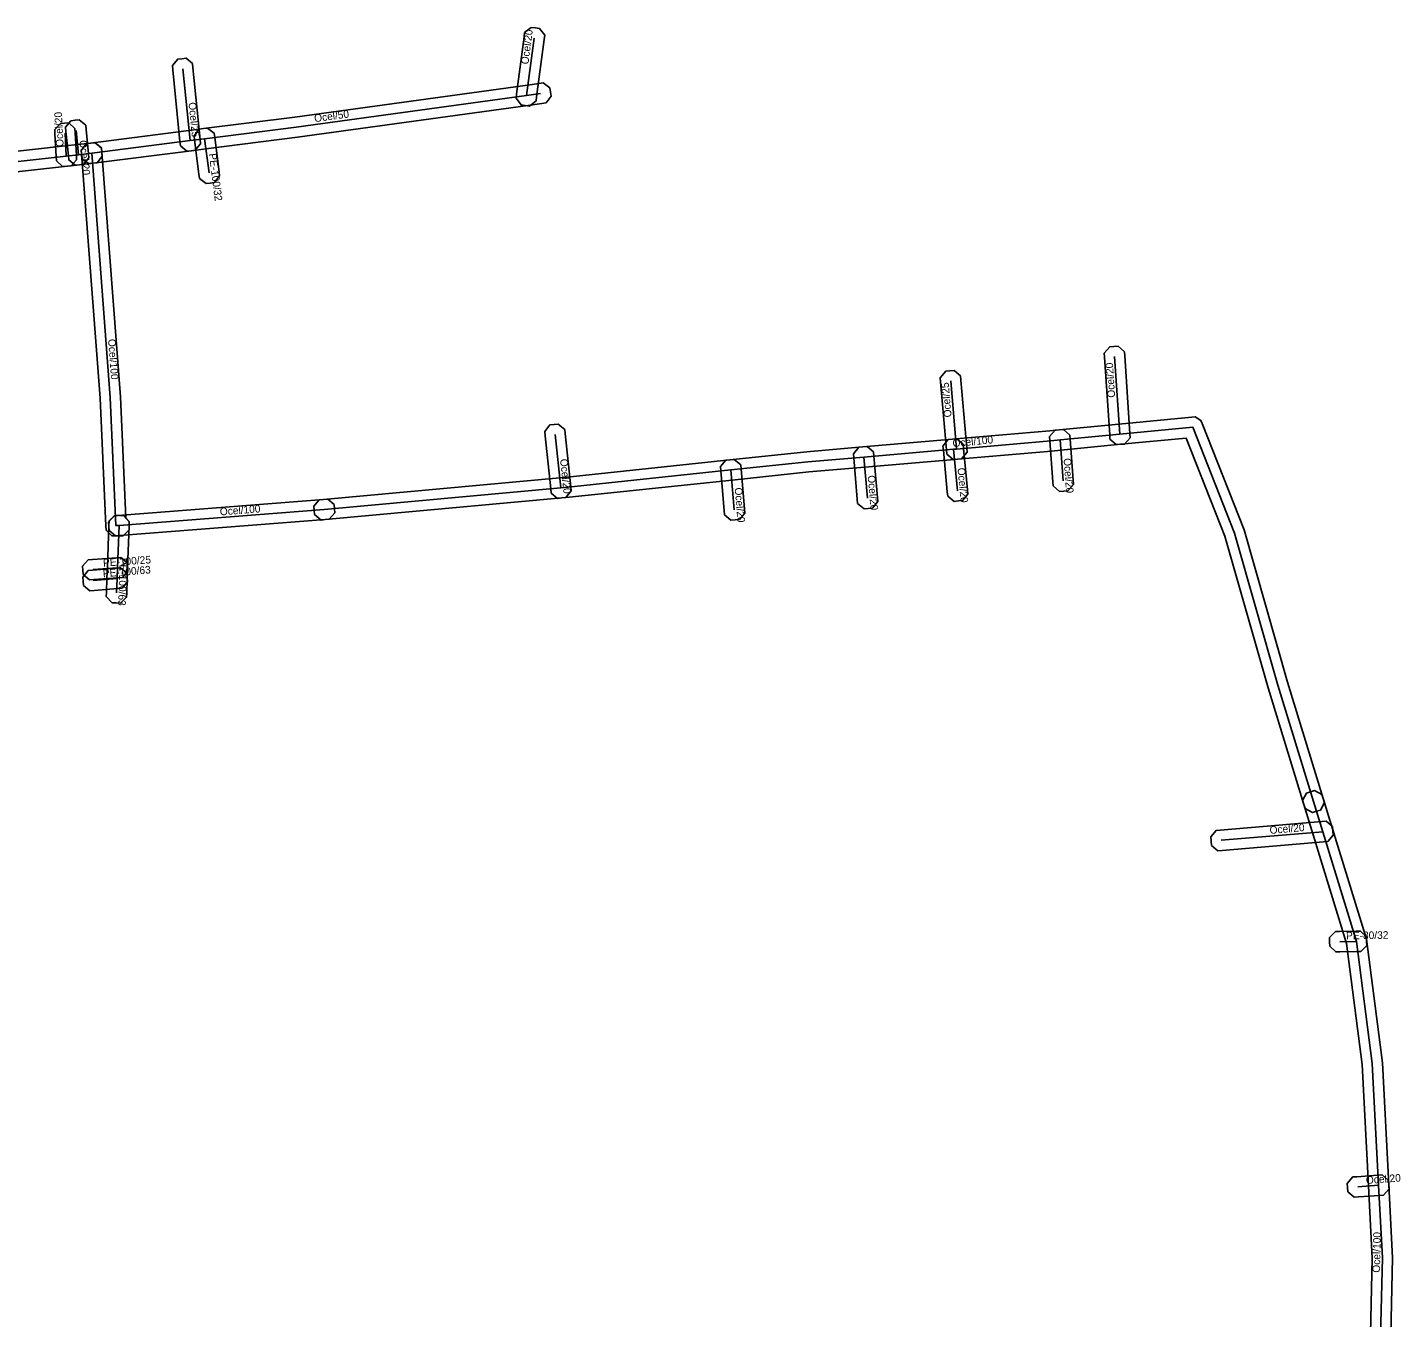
# Model space of a CAD drawing. Extents: x -569373 to -565022, y -1135090 to -1131496.
# Drawn here: x -565577.8 to -565442.3, y -1133706.4 to -1133579.1 of the extents above; entities that cross this region are included whole.
import ezdxf

# ---------------------------------------------------------------- set-up
doc = ezdxf.new("R2010")
doc.units = 0
for name, color, linetype in [('1', 7, 'Continuous'), ('24', 7, 'Continuous'), ('30', 7, 'Continuous')]:
    doc.layers.add(name, color=color, linetype=linetype)

msp = doc.modelspace()

# ---------------------------------------------------------------- linework, layer by layer
at = {"layer": '1'}
for points in [[(-565526.775, -1133579.909), (-565526.828, -1133580.32), (-565527.568, -1133585.98), (-565527.622, -1133586.39), (-565528.279, -1133586.895), (-565528.69, -1133586.842), (-565529.1, -1133586.788), (-565529.605, -1133586.131), (-565529.552, -1133585.72), (-565528.812, -1133580.06), (-565528.758, -1133579.65), (-565528.101, -1133579.145), (-565527.69, -1133579.198), (-565527.28, -1133579.252)], [(-565562.714, -1133590.822), (-565562.755, -1133590.41), (-565563.465, -1133583.32), (-565563.506, -1133582.908), (-565562.982, -1133582.266), (-565562.57, -1133582.225), (-565562.158, -1133582.184), (-565561.516, -1133582.708), (-565561.475, -1133583.12), (-565560.765, -1133590.21), (-565560.724, -1133590.622), (-565561.248, -1133591.264), (-565561.66, -1133591.305), (-565562.072, -1133591.346)], [(-565571.998, -1133590.611), (-565571.587, -1133590.558), (-565561.889, -1133589.318), (-565560.449, -1133589.128), (-565551.431, -1133587.979), (-565528.697, -1133584.859), (-565527.327, -1133584.669), (-565526.917, -1133584.612), (-565526.256, -1133585.113), (-565526.199, -1133585.523), (-565526.142, -1133585.933), (-565526.643, -1133586.594), (-565527.053, -1133586.651), (-565528.423, -1133586.841), (-565551.169, -1133589.961), (-565560.191, -1133591.112), (-565561.631, -1133591.302), (-565571.333, -1133592.542), (-565571.744, -1133592.595), (-565572.399, -1133592.088), (-565572.452, -1133591.677), (-565572.505, -1133591.266)], [(-565572.056, -1133588.788), (-565572.015, -1133589.2), (-565571.775, -1133591.6), (-565571.734, -1133592.013), (-565572.258, -1133592.654), (-565572.67, -1133592.695), (-565573.083, -1133592.736), (-565573.724, -1133592.212), (-565573.765, -1133591.8), (-565574.005, -1133589.4), (-565574.046, -1133588.987), (-565573.522, -1133588.346), (-565573.11, -1133588.305), (-565572.697, -1133588.264)], [(-565574.947, -1133592.297), (-565574.969, -1133591.883), (-565575.089, -1133589.633), (-565575.111, -1133589.22), (-565574.557, -1133588.603), (-565574.143, -1133588.581), (-565573.73, -1133588.559), (-565573.113, -1133589.113), (-565573.091, -1133589.527), (-565572.971, -1133591.777), (-565572.949, -1133592.19), (-565573.503, -1133592.807), (-565573.917, -1133592.829), (-565574.33, -1133592.851)], [(-565559.38, -1133589.583), (-565559.328, -1133589.994), (-565558.898, -1133593.374), (-565558.846, -1133593.785), (-565559.353, -1133594.44), (-565559.764, -1133594.492), (-565560.175, -1133594.544), (-565560.83, -1133594.037), (-565560.882, -1133593.626), (-565561.312, -1133590.246), (-565561.364, -1133589.835), (-565560.857, -1133589.18), (-565560.446, -1133589.128), (-565560.035, -1133589.076)], [(-565616.839, -1133596.218), (-565616.429, -1133596.16), (-565599.549, -1133593.79), (-565595.205, -1133593.178), (-565574.079, -1133590.836), (-565572.881, -1133590.706), (-565571.574, -1133590.556), (-565571.162, -1133590.509), (-565570.513, -1133591.025), (-565570.466, -1133591.436), (-565570.419, -1133591.848), (-565570.935, -1133592.497), (-565571.346, -1133592.544), (-565572.659, -1133592.694), (-565573.861, -1133592.824), (-565594.955, -1133595.162), (-565599.271, -1133595.77), (-565616.151, -1133598.14), (-565616.561, -1133598.198), (-565617.222, -1133597.699), (-565617.28, -1133597.289), (-565617.338, -1133596.879)], [(-565568.632, -1133615.58), (-565568.102, -1133627.534), (-565567.77, -1133627.866), (-565567.77, -1133628.28), (-565567.77, -1133628.694), (-565568.356, -1133629.28), (-565568.77, -1133629.28), (-565569.07, -1133629.28), (-565569.471, -1133629.28), (-565570.051, -1133628.725), (-565570.069, -1133628.324), (-565570.628, -1133615.7), (-565572.457, -1133591.626), (-565572.488, -1133591.213), (-565571.949, -1133590.584), (-565571.536, -1133590.553), (-565571.123, -1133590.522), (-565570.494, -1133591.061), (-565570.463, -1133591.474)], [(-565471.01, -1133619.749), (-565471.038, -1133619.336), (-565471.548, -1133611.676), (-565471.575, -1133611.263), (-565471.029, -1133610.64), (-565470.616, -1133610.612), (-565470.203, -1133610.585), (-565469.58, -1133611.131), (-565469.552, -1133611.544), (-565469.042, -1133619.204), (-565469.015, -1133619.617), (-565469.561, -1133620.24), (-565469.974, -1133620.268), (-565470.387, -1133620.295)], [(-565487.1, -1133621.229), (-565487.136, -1133620.816), (-565487.716, -1133614.106), (-565487.752, -1133613.693), (-565487.219, -1133613.06), (-565486.806, -1133613.024), (-565486.393, -1133612.988), (-565485.76, -1133613.521), (-565485.724, -1133613.934), (-565485.144, -1133620.644), (-565485.108, -1133621.057), (-565485.641, -1133621.69), (-565486.054, -1133621.726), (-565486.467, -1133621.762)], [(-565549.024, -1133625.742), (-565548.611, -1133625.704), (-565525.283, -1133623.564), (-565524.549, -1133623.495), (-565508.505, -1133621.806), (-565500.916, -1133621.005), (-565495.376, -1133620.524), (-565486.541, -1133619.764), (-565486.231, -1133619.734), (-565476.952, -1133618.934), (-565476.037, -1133618.845), (-565470.136, -1133618.275), (-565462.935, -1133617.585), (-565462.602, -1133617.553), (-565462.032, -1133617.903), (-565461.91, -1133618.214), (-565457.782, -1133628.699), (-565453.501, -1133643.736), (-565449.974, -1133655.216), (-565449.852, -1133655.612), (-565450.24, -1133656.344), (-565450.636, -1133656.466), (-565451.032, -1133656.588), (-565451.764, -1133656.2), (-565451.886, -1133655.804), (-565455.419, -1133644.304), (-565459.678, -1133629.341), (-565463.495, -1133619.647), (-565469.944, -1133620.265), (-565475.843, -1133620.835), (-565476.768, -1133620.926), (-565486.049, -1133621.726), (-565486.359, -1133621.756), (-565495.204, -1133622.516), (-565500.724, -1133622.995), (-565508.295, -1133623.794), (-565524.351, -1133625.485), (-565525.097, -1133625.556), (-565548.429, -1133627.696), (-565548.841, -1133627.734), (-565549.478, -1133627.204), (-565549.516, -1133626.791), (-565549.554, -1133626.379)], [(-565524.788, -1133618.794), (-565524.745, -1133619.206), (-565524.195, -1133624.456), (-565524.152, -1133624.868), (-565524.674, -1133625.512), (-565525.086, -1133625.555), (-565525.498, -1133625.598), (-565526.142, -1133625.076), (-565526.185, -1133624.664), (-565526.735, -1133619.414), (-565526.778, -1133619.002), (-565526.256, -1133618.358), (-565525.844, -1133618.315), (-565525.432, -1133618.272)], [(-565474.974, -1133619.353), (-565474.943, -1133619.766), (-565474.643, -1133623.806), (-565474.612, -1133624.219), (-565475.153, -1133624.846), (-565475.566, -1133624.877), (-565475.979, -1133624.908), (-565476.606, -1133624.367), (-565476.637, -1133623.954), (-565476.937, -1133619.914), (-565476.968, -1133619.501), (-565476.427, -1133618.874), (-565476.014, -1133618.843), (-565475.601, -1133618.812)], [(-565494.329, -1133621.021), (-565494.294, -1133621.434), (-565493.944, -1133625.504), (-565493.908, -1133625.917), (-565494.441, -1133626.551), (-565494.854, -1133626.586), (-565495.267, -1133626.622), (-565495.901, -1133626.089), (-565495.936, -1133625.676), (-565496.286, -1133621.606), (-565496.322, -1133621.193), (-565495.789, -1133620.559), (-565495.376, -1133620.524), (-565494.963, -1133620.488)], [(-565485.493, -1133620.253), (-565485.454, -1133620.665), (-565485.064, -1133624.765), (-565485.025, -1133625.178), (-565485.553, -1133625.817), (-565485.965, -1133625.856), (-565486.378, -1133625.895), (-565487.017, -1133625.367), (-565487.056, -1133624.955), (-565487.446, -1133620.855), (-565487.485, -1133620.442), (-565486.957, -1133619.803), (-565486.545, -1133619.764), (-565486.132, -1133619.725)], [(-565507.438, -1133622.303), (-565507.404, -1133622.716), (-565507.074, -1133626.636), (-565507.039, -1133627.049), (-565507.573, -1133627.682), (-565507.986, -1133627.716), (-565508.399, -1133627.751), (-565509.032, -1133627.217), (-565509.066, -1133626.804), (-565509.396, -1133622.884), (-565509.431, -1133622.471), (-565508.897, -1133621.838), (-565508.484, -1133621.804), (-565508.071, -1133621.769)], [(-565569.261, -1133627.315), (-565568.848, -1133627.283), (-565548.598, -1133625.703), (-565548.185, -1133625.671), (-565547.555, -1133626.209), (-565547.523, -1133626.622), (-565547.491, -1133627.035), (-565548.029, -1133627.665), (-565548.442, -1133627.697), (-565568.692, -1133629.277), (-565569.105, -1133629.309), (-565569.735, -1133628.771), (-565569.767, -1133628.358), (-565569.799, -1133627.945)], [(-565567.756, -1133627.902), (-565567.771, -1133628.316), (-565567.921, -1133632.487), (-565567.961, -1133633.527), (-565568.011, -1133634.945), (-565568.025, -1133635.359), (-565568.631, -1133635.924), (-565569.045, -1133635.909), (-565569.459, -1133635.895), (-565570.024, -1133635.289), (-565570.009, -1133634.875), (-565569.959, -1133633.453), (-565569.919, -1133632.413), (-565569.769, -1133628.244), (-565569.754, -1133627.83), (-565569.148, -1133627.266), (-565568.734, -1133627.281), (-565568.32, -1133627.296)], [(-565571.813, -1133631.651), (-565571.4, -1133631.622), (-565568.99, -1133631.452), (-565568.577, -1133631.423), (-565567.951, -1133631.967), (-565567.922, -1133632.38), (-565567.893, -1133632.793), (-565568.437, -1133633.419), (-565568.85, -1133633.448), (-565571.26, -1133633.618), (-565571.673, -1133633.647), (-565572.299, -1133633.103), (-565572.328, -1133632.69), (-565572.357, -1133632.277)], [(-565571.808, -1133632.729), (-565571.395, -1133632.694), (-565569.045, -1133632.494), (-565568.632, -1133632.459), (-565567.999, -1133632.992), (-565567.964, -1133633.405), (-565567.929, -1133633.818), (-565568.462, -1133634.451), (-565568.875, -1133634.486), (-565571.225, -1133634.686), (-565571.638, -1133634.721), (-565572.271, -1133634.188), (-565572.306, -1133633.775), (-565572.341, -1133633.362)], [(-565449.522, -1133659.441), (-565449.935, -1133659.476), (-565459.955, -1133660.326), (-565460.368, -1133660.361), (-565461.001, -1133659.828), (-565461.036, -1133659.415), (-565461.071, -1133659.002), (-565460.538, -1133658.369), (-565460.125, -1133658.334), (-565450.105, -1133657.484), (-565449.692, -1133657.449), (-565449.059, -1133657.982), (-565449.024, -1133658.395), (-565448.989, -1133658.808)], [(-565448.772, -1133668.337), (-565448.358, -1133668.33), (-565446.708, -1133668.3), (-565446.294, -1133668.293), (-565445.697, -1133668.868), (-565445.69, -1133669.282), (-565445.683, -1133669.696), (-565446.258, -1133670.293), (-565446.672, -1133670.3), (-565448.322, -1133670.33), (-565448.736, -1133670.337), (-565449.333, -1133669.762), (-565449.34, -1133669.348), (-565449.347, -1133668.934)], [(-565444.024, -1133694.327), (-565444.437, -1133694.357), (-565446.497, -1133694.507), (-565446.91, -1133694.537), (-565447.537, -1133693.996), (-565447.567, -1133693.583), (-565447.597, -1133693.17), (-565447.056, -1133692.543), (-565446.643, -1133692.513), (-565444.583, -1133692.363), (-565444.17, -1133692.333), (-565443.543, -1133692.874), (-565443.513, -1133693.287), (-565443.483, -1133693.7)]]:
    msp.add_lwpolyline(points, close=True, dxfattribs=at)
msp.add_lwpolyline([(-565445.35, -1133709.527), (-565445.141, -1133700.544), (-565445.509, -1133693.412), (-565446.127, -1133681.45), (-565447.671, -1133669.513), (-565450.976, -1133658.774), (-565451.886, -1133655.803), (-565452.007, -1133655.407), (-565451.619, -1133654.675), (-565451.223, -1133654.554), (-565450.827, -1133654.433), (-565450.095, -1133654.821), (-565449.974, -1133655.217), (-565449.064, -1133658.186), (-565445.709, -1133669.087), (-565444.133, -1133681.27), (-565443.511, -1133693.308), (-565443.139, -1133700.516), (-565443.35, -1133709.573)], dxfattribs=at)
at = {"layer": '24'}
for points in [[(-565527.82, -1133580.19), (-565528.56, -1133585.85)], [(-565561.76, -1133590.31), (-565562.47, -1133583.22)], [(-565571.46, -1133591.55), (-565561.76, -1133590.31), (-565560.32, -1133590.12), (-565551.3, -1133588.97), (-565528.56, -1133585.85), (-565527.19, -1133585.66)], [(-565573.97, -1133591.83), (-565574.09, -1133589.58)], [(-565573.01, -1133589.3), (-565572.77, -1133591.7)], [(-565560.32, -1133590.12), (-565559.89, -1133593.5)], [(-565616.29, -1133597.15), (-565599.41, -1133594.78), (-565595.08, -1133594.17), (-565573.97, -1133591.83), (-565572.77, -1133591.7), (-565571.46, -1133591.55)], [(-565571.46, -1133591.55), (-565569.63, -1133615.64), (-565569.07, -1133628.28), (-565568.77, -1133628.28)], [(-565470.04, -1133619.27), (-565470.55, -1133611.61)], [(-565486.14, -1133620.73), (-565486.72, -1133614.02)], [(-565548.52, -1133626.7), (-565525.19, -1133624.56), (-565524.45, -1133624.49), (-565508.4, -1133622.8), (-565500.82, -1133622), (-565495.29, -1133621.52), (-565486.45, -1133620.76), (-565486.14, -1133620.73), (-565476.86, -1133619.93), (-565475.94, -1133619.84), (-565470.04, -1133619.27), (-565462.84, -1133618.58), (-565458.73, -1133629.02), (-565454.46, -1133644.02), (-565450.93, -1133655.51)], [(-565525.74, -1133619.31), (-565525.19, -1133624.56)], [(-565486.45, -1133620.76), (-565486.06, -1133624.86)], [(-565475.94, -1133619.84), (-565475.64, -1133623.88)], [(-565495.29, -1133621.52), (-565494.94, -1133625.59)], [(-565508.4, -1133622.8), (-565508.07, -1133626.72)], [(-565568.77, -1133628.28), (-565548.52, -1133626.7)], [(-565568.77, -1133628.28), (-565568.92, -1133632.45), (-565568.96, -1133633.49), (-565569.01, -1133634.91)], [(-565571.33, -1133632.62), (-565568.92, -1133632.45)], [(-565571.31, -1133633.69), (-565568.96, -1133633.49)], [(-565458.04, -1133740.39), (-565454.69, -1133739.19), (-565445.25, -1133736.28), (-565444.55, -1133718.24), (-565444.35, -1133709.55), (-565444.14, -1133700.53), (-565444.51, -1133693.36), (-565445.13, -1133681.36), (-565446.69, -1133669.3), (-565450.02, -1133658.48), (-565450.93, -1133655.51)], [(-565450.02, -1133658.48), (-565460.04, -1133659.33)], [(-565448.34, -1133669.33), (-565446.69, -1133669.3)], [(-565444.51, -1133693.36), (-565446.57, -1133693.51)]]:
    msp.add_lwpolyline(points, dxfattribs=at)

# ---------------------------------------------------------------- texts
at = {"layer": '30'}
for s, rotation, p in [('Ocel/20', 82.55128, (-565528.39, -1133582.82)), ('Ocel/25', 275.71859, (-565561.915, -1133586.565)), ('Ocel/20', 93.05288, (-565574.23, -1133590.905)), ('Ocel/50', 7.81238, (-565549.463, -1133588.491)), ('Ocel/20', 275.71059, (-565572.69, -1133590.3)), ('PE-100/32', 277.25016, (-565559.905, -1133591.61)), ('Ocel/100', 274.34414, (-565569.851, -1133609.902)), ('Ocel/20', 93.80911, (-565470.495, -1133615.64)), ('Ocel/25', 94.94026, (-565486.63, -1133617.575)), ('Ocel/100', 5.52754, (-565486.505, -1133620.546)), ('Ocel/20', 275.9806, (-565525.265, -1133621.735)), ('Ocel/20', 274.24684, (-565475.59, -1133621.66)), ('Ocel/20', 274.91506, (-565494.915, -1133623.355)), ('Ocel/20', 275.43374, (-565486.055, -1133622.61)), ('Ocel/20', 274.81202, (-565508.035, -1133624.56)), ('Ocel/100', 4.46145, (-565558.795, -1133627.286)), ('PE-100/25', 4.03493, (-565570.325, -1133632.335)), ('PE-100/63', 267.93989, (-565568.691, -1133631.445)), ('PE-100/63', 4.86451, (-565570.335, -1133633.39)), ('Ocel/20', 4.84881, (-565455.23, -1133658.705)), ('PE-80/32', 1.04163, (-565447.715, -1133669.115)), ('Ocel/20', 4.16467, (-565445.74, -1133693.235)), ('Ocel/100', 88.6663, (-565444.379, -1133701.991))]:
    msp.add_text(s, height=0.75, rotation=rotation, dxfattribs=at).set_placement(p)

doc.saveas('drawing.dxf')
